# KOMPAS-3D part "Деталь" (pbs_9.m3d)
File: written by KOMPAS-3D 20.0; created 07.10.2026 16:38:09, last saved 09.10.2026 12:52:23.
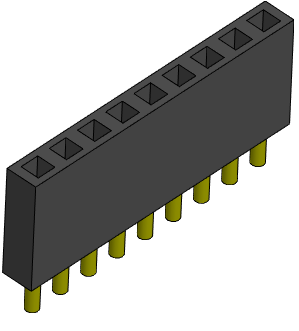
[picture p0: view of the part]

Document properties: Полное имя файла: D:\myProjects\Progect_esp32\box_compas\pbs_9.m3d

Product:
- Part/product: Деталь
    Масса: 0.00277694

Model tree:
1. Эскиз:1
2. Элемент выдавливания:1
     Расстояние 1 = 8.5
3. Эскиз:2  (with: Элемент выдавливания:1)
4. Элемент выдавливания:2
     Расстояние 1 = 3
5. Массив по сетке:2  (with: Элемент выдавливания:2, Эскиз:2)  (9 pattern instances)
     Шаг 1 = 2.54; Угол раствора = 90
6. Эскиз:3  (with: Элемент выдавливания:1)
7. Элемент выдавливания:3
     Расстояние 2 = 8
8. Массив по сетке:3  (with: Элемент выдавливания:3, Эскиз:3)  (9 pattern instances)
     Шаг 1 = 2.54; Угол раствора = 90; Геометрический массив = 128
